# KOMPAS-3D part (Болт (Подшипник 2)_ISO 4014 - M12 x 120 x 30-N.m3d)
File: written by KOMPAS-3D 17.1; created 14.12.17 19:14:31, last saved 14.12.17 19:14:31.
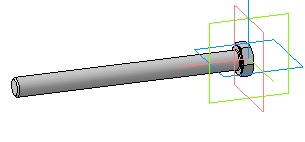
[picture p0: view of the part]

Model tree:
1. Операция без истории:1  (labels: Болт (Подшипник 2)_ISO 4014 - M12 x 120 x 30-N)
